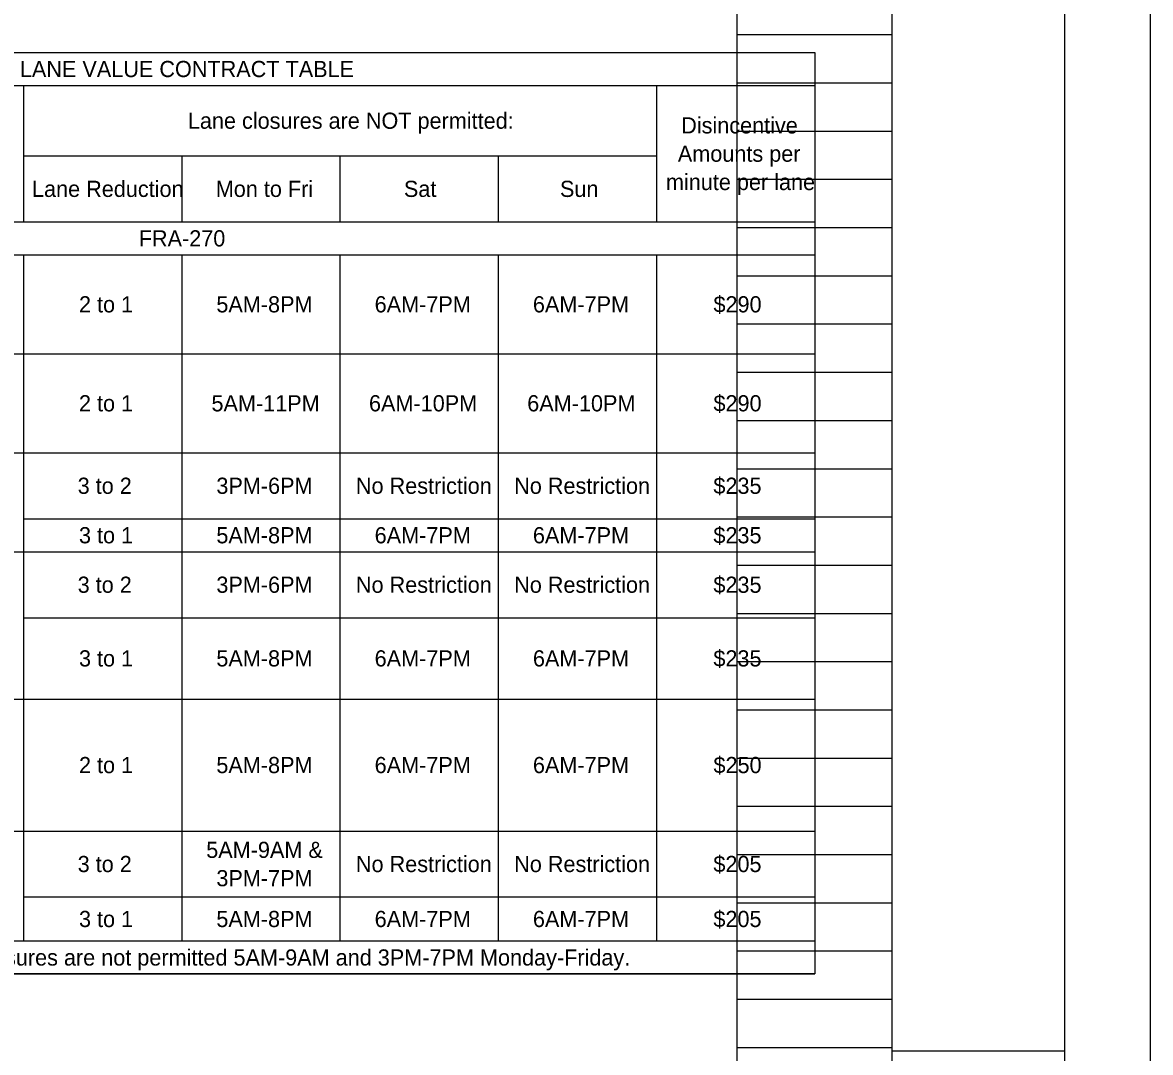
# Model space of a CAD drawing. Extents: x 0 to 34, y 0 to 22.
# Drawn here: x 27.45 to 34, y 5.99 to 11.97 of the extents above; entities that cross this region are included whole.
import ezdxf

# ---------------------------------------------------------------- set-up
doc = ezdxf.new("R2010")
doc.units = 0
for name, color, linetype in [('Default', 7, 'Continuous'), ('SH_Border', 7, 'Continuous'), ('SH_Cut_Line', 7, 'Continuous'), ('SH_Data', 7, 'Continuous')]:
    doc.layers.add(name, color=color, linetype=linetype)

msp = doc.modelspace()

# ---------------------------------------------------------------- linework, layer by layer
at = {"layer": 'Default'}
for p, q in [((24.67, 11.7962), (32.05, 11.7962)), ((32.05, 11.7962), (32.05, 6.4464)), ((24.67, 11.6047), (32.05, 11.6047)), ((27.4535, 11.6047), (27.4535, 10.8131)), ((31.1307, 11.6047), (31.1307, 10.8131)), ((27.4535, 11.1961), (31.1307, 11.1961)), ((28.3728, 11.1961), (28.3728, 10.8131)), ((29.2921, 11.1961), (29.2921, 10.8131)), ((30.2114, 11.1961), (30.2114, 10.8131)), ((24.67, 10.8131), (32.05, 10.8131)), ((24.67, 10.6215), (32.05, 10.6215)), ((27.4535, 10.6215), (27.4535, 6.6379)), ((28.3728, 10.6215), (28.3728, 6.6379)), ((29.2921, 10.6215), (29.2921, 6.6379)), ((30.2114, 10.6215), (30.2114, 6.6379)), ((31.1307, 10.6215), (31.1307, 6.6379)), ((24.67, 10.047), (32.05, 10.047)), ((24.67, 9.4724), (32.05, 9.4724)), ((27.4535, 9.0894), (32.05, 9.0894)), ((24.67, 8.8978), (32.05, 8.8978)), ((27.4535, 8.5148), (32.05, 8.5148)), ((24.67, 8.0424), (32.05, 8.0424)), ((24.67, 7.2763), (32.05, 7.2763)), ((27.4535, 6.8932), (32.05, 6.8932)), ((24.67, 6.6379), (32.05, 6.6379)), ((24.67, 6.4464), (32.05, 6.4464))]:
    msp.add_line(p, q, dxfattribs=at)
msp.add_lwpolyline([(24.67, 11.7962), (32.05, 11.7962), (32.05, 6.4464), (24.67, 6.4464)], close=True, dxfattribs=at)
at = {"layer": 'SH_Border'}
for p, q in [((32.5, 0.5), (32.5, 21.5)), ((32.5, 6), (33.5, 6))]:
    msp.add_line(p, q, dxfattribs=at)
msp.add_lwpolyline([(2, 21.5), (33.5, 21.5), (33.5, 0.5), (2, 0.5)], close=True, dxfattribs=at)
at = {"layer": 'SH_Cut_Line'}
msp.add_lwpolyline([(0, 0), (34, 0), (34, 22), (0, 22)], close=True, dxfattribs=at)
at = {"layer": 'SH_Data'}
for p, q in [((31.6, 0.98), (31.6, 21.14)), ((32.5, 0.98), (32.5, 21.14)), ((31.6, 11.9), (32.5, 11.9)), ((31.6, 11.62), (32.5, 11.62)), ((31.6, 11.34), (32.5, 11.34)), ((31.6, 11.06), (32.5, 11.06)), ((31.6, 10.78), (32.5, 10.78)), ((31.6, 10.5), (32.5, 10.5)), ((31.6, 10.22), (32.5, 10.22)), ((31.6, 9.94), (32.5, 9.94)), ((31.6, 9.66), (32.5, 9.66)), ((31.6, 9.38), (32.5, 9.38)), ((31.6, 9.1), (32.5, 9.1)), ((31.6, 8.82), (32.5, 8.82)), ((31.6, 8.54), (32.5, 8.54)), ((31.6, 8.26), (32.5, 8.26)), ((31.6, 7.98), (32.5, 7.98)), ((31.6, 7.7), (32.5, 7.7)), ((31.6, 7.42), (32.5, 7.42)), ((31.6, 7.14), (32.5, 7.14)), ((31.6, 6.86), (32.5, 6.86)), ((31.6, 6.58), (32.5, 6.58)), ((31.6, 6.3), (32.5, 6.3)), ((31.6, 6.02), (32.5, 6.02))]:
    msp.add_line(p, q, dxfattribs=at)

# ---------------------------------------------------------------- texts
at = {"layer": 'Default'}
for s, height, p in [('LANE VALUE CONTRACT TABLE', 0.093974, (27.4328, 11.6535)), ('Lane closures are NOT permitted:', 0.093974, (28.4086, 11.3534)), ('Disincentive ', 0.093974, (31.2743, 11.3263)), ('Amounts per ', 0.093974, (31.2547, 11.1619)), ('minute per lane', 0.093974, (31.1857, 10.9974)), ('Lane Reduction', 0.093974, (27.5034, 10.9576)), ('Mon to Fri', 0.09397, (28.5706, 10.9576)), ('Sat', 0.09397, (29.6635, 10.9576)), ('Sun', 0.09397, (30.57, 10.9576)), ('FRA-270', 0.09397, (28.1233, 10.6703)), ('2 to 1', 0.09397, (27.7762, 10.2873)), ('5AM-8PM', 0.09397, (28.5742, 10.2873)), ('6AM-7PM', 0.09397, (29.4936, 10.2873)), ('6AM-7PM', 0.09397, (30.4129, 10.2873)), ('$290', 0.09397, (31.4618, 10.2873)), ('2 to 1', 0.09397, (27.7762, 9.7127)), ('5AM-11PM', 0.09397, (28.5458, 9.7127)), ('6AM-10PM', 0.09397, (29.4607, 9.7127)), ('6AM-10PM', 0.09397, (30.38, 9.7127)), ('$290', 0.09397, (31.4618, 9.7127)), ('3 to 2', 0.09397, (27.7685, 9.2339)), ('3PM-6PM', 0.09397, (28.5742, 9.2339)), ('No Restriction', 0.093974, (29.3848, 9.2339)), ('No Restriction', 0.093974, (30.3041, 9.2339)), ('$235', 0.09397, (31.4613, 9.2339)), ('3 to 1', 0.09397, (27.7762, 8.9466)), ('5AM-8PM', 0.09397, (28.5742, 8.9466)), ('6AM-7PM', 0.09397, (29.4936, 8.9466)), ('6AM-7PM', 0.09397, (30.4129, 8.9466)), ('$235', 0.09397, (31.4613, 8.9466)), ('3 to 2', 0.09397, (27.7685, 8.6593)), ('3PM-6PM', 0.09397, (28.5742, 8.6593)), ('No Restriction', 0.093974, (29.3848, 8.6593)), ('No Restriction', 0.093974, (30.3041, 8.6593)), ('$235', 0.09397, (31.4613, 8.6593)), ('3 to 1', 0.09397, (27.7762, 8.2316)), ('5AM-8PM', 0.09397, (28.5742, 8.2316)), ('6AM-7PM', 0.09397, (29.4936, 8.2316)), ('6AM-7PM', 0.09397, (30.4129, 8.2316)), ('$235', 0.09397, (31.4613, 8.2316)), ('2 to 1', 0.09397, (27.7762, 7.6123)), ('5AM-8PM', 0.09397, (28.5742, 7.6123)), ('6AM-7PM', 0.09397, (29.4936, 7.6123)), ('6AM-7PM', 0.09397, (30.4129, 7.6123)), ('$250', 0.09397, (31.4618, 7.6123)), ('5AM-9AM & ', 0.09397, (28.5153, 7.12)), ('3 to 2', 0.09397, (27.7685, 7.0378)), ('No Restriction', 0.093974, (29.3848, 7.0378)), ('No Restriction', 0.093974, (30.3041, 7.0378)), ('$205', 0.09397, (31.4613, 7.0378)), ('3PM-7PM', 0.09397, (28.5742, 6.9555)), ('3 to 1', 0.09397, (27.7762, 6.7186)), ('5AM-8PM', 0.09397, (28.5742, 6.7186)), ('6AM-7PM', 0.09397, (29.4936, 6.7186)), ('6AM-7PM', 0.09397, (30.4129, 6.7186)), ('$205', 0.09397, (31.4613, 6.7186)), ('Short term shoulder closures are not permitted 5AM-9AM and 3PM-7PM Monday-Friday.', 0.093974, (26.0475, 6.4951))]:
    msp.add_text(s, height=height, dxfattribs=at).set_placement(p)

doc.saveas('drawing.dxf')
